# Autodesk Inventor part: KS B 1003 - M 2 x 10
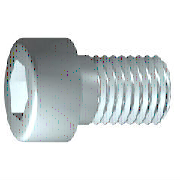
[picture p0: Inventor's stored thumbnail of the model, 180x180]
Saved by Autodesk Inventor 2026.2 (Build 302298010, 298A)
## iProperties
Created: 2025-01
Part Number: KS B 1003 - M 2 x 10
Material: 강철, 연강
Description: 6각머리 태핑 나사
Document SubType Name: Modeling
Standard: KS B 1003
Designer: work
Standards Organization: KS
Language: ko-KR
Size Designation: M 2 x 10
Categories: <MemberInstance><Categories><Category DisplayName="조임쇠" InternalName="e4da775c-781d-43d5-af7c-5136215cf5a6" Mnemonic="FSTN"><Category DisplayName="볼트" InternalN
Density: 7.85 g/cm^3
Appearance: 반연마
IsCustomPart: 1
Author: work
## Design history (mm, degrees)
workplane "Work Plane1"
fillet "Fillet2" dims "d30" = 0.1 (= R)
revolve "본체" stored, may be unused: angle "d10" = 90 deg
sketch "스케치2"
  geometry: L1 (0, -2.66)-(0, 2.66) reference; L2 (-2.66, 0)-(2.66, 0) reference; L3 (0.866, 0)-(0.433, -0.75); L4 (0.433, -0.75)-(-0.433, -0.75); L5 (-0.433, -0.75)-(-0.866, 0); L6 (-0.866, 0)-(-0.433, 0.75); L7 (-0.433, 0.75)-(0.433, 0.75); L8 (0.433, 0.75)-(0.866, 0); 2 further points
  constraints: 12 end point, 1 coincident, 1 horizontal alignment, 1 point on line, 12 other
extrude "슬롯" join sketch "스케치2" stored distance "d11" = 10; taper "d12" = 0 deg
body "Solid1"
fillet "모깎기1" dims "d17" = 0.2 (= RR)
feature "스레드" dims "d13" = 9 (= GEL), "d14" = 0
chamfer "모따기1" distance "d15" = 0.24538 (= -0.5 x SPD + 0.5 x GD); stored, may be unused: second distance "d16" = 0.24538 (= GUL), angle "d27" = 45 deg
sketch "스케치1"
  geometry: L1 (-0.5, 0)-(10, 0); L2 (10, 0)-(10, 1); L3 (10, 1)-(1, 1); L4 (1, 1)-(0.755, 1); L5 (0.755, 1)-(0, 1); L6 (0, 1)-(0, 1.9); L7 (0, 1.9)-(-2, 1.9); L8 (-2, 1.9)-(-2, 0.866); L9 (-2, 0.866)-(-1, 0.866); L10 (-1, 0.866)-(-0.5, 0); L11 (-4.4, 0)-(12.4, 0) reference; L12 (0, -0.38)-(0, 2.28) reference; L13 (1, 1)-(0, 1)
  constraints: 22 end point, 6 parallel, 2 collinear, 2 perpendicular, 1 horizontal, 1 point on line
  dimensions: "d1" = 9 distance from line of L3.end L2 (= GEL); "d2" = 0.24548 distance of L4.end L3.end (computed from GAL); "d3" = 2 distance between parallel lines of L8 L6 (= KOH); "d4" = 1 distance of L8.end L9.end (= INTI); "d5" = 60 deg angle of L10 L1; "d6" = 2 diameter of L3 L1 (= GD); "d7" = 2 diameter of L5 L1 (= BDM); "d8" = 1.73205 diameter of L9 L1 (= 1.1547 x SW); "d9" = 3.8 diameter of L7 L1 (= KOD); "d26" = 10 distance between parallel lines of L12 L2 (= NLG)
other parameters: "GD" = 2 (= NND) [user parameter; used in 2 equation terms], "NLG" = 10 [user parameter; used in 1 equation term], "GEL" = 9 [user parameter; used in 2 equation terms], "KOD" = 3.8 [user parameter; used in 1 equation term], "KOH" = 2 [user parameter; used in 1 equation term], "INTI" = 1 [user parameter; used in 1 equation term], "GAL" = 0.24538 (= 0.61345 x PTC) [user parameter; used in 1 equation term], "GUL" = 0.24538 (= 0.61345 x PTC) [user parameter; used in 1 equation term], "BDM" = 2 (= NND) [user parameter; used in 1 equation term], "SW" = 1.5 [user parameter; used in 2 equation terms], "RR" = 0.2 [user parameter; used in 1 equation term], "SPD" = 1.50924 (= NND - 1.2269 x PTC) [user parameter; used in 1 equation term], "d19" = 0, "d28" = 0, "d29" = 0, "R" = 0.1 [user parameter; used in 1 equation term], "PHH" = 0.1 [user parameter], "GD1" = 1.50924 (= THREADDIA - 1.2269 x PTC) [user parameter], "THREADDIA" = 2 [user parameter; used in 1 equation term], "FAWI" = 45 deg [user parameter], "TPU" = 25 (computed from PTC) [user parameter], "PTC" = 0.4 [user parameter; used in 5 equation terms], "NND" = 2 [user parameter; used in 3 equation terms], "TOA" = 30 deg [user parameter], "E0" = 1.7325 (= 1.155 x SW) [user parameter]
